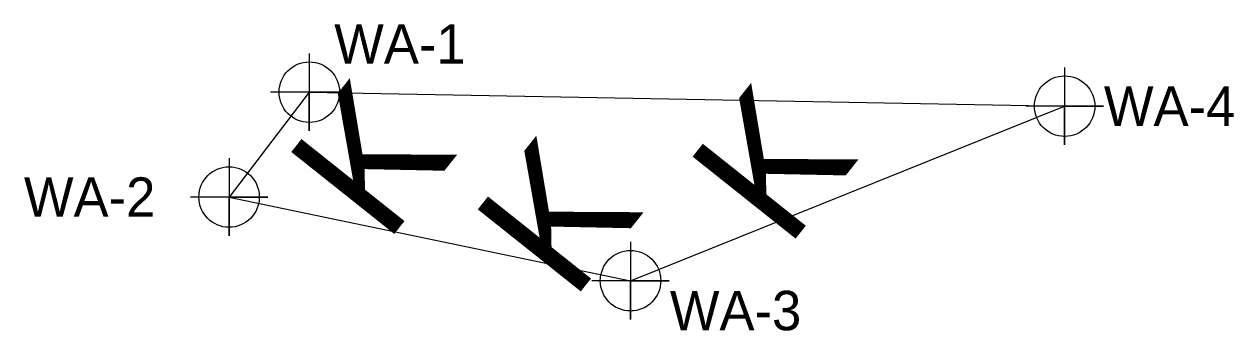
# Model space of a CAD drawing. Extents: x 1487542 to 1488992, y 498221 to 499418.
# Drawn here: x 1488898 to 1488991.8, y 499394.7 to 499418.4 of the extents above; entities that cross this region are included whole.
import ezdxf

# ---------------------------------------------------------------- set-up
doc = ezdxf.new("R2010")
doc.units = 0
for name, color, linetype in [('Exist Environmental Wetland Boundary', 7, 'Continuous'), ('Exist Environmental Wetland Boundary Cogo Point CELL', 7, 'Continuous'), ('Exist Environmental Wetland Boundary Text', 7, 'Continuous')]:
    doc.layers.add(name, color=color, linetype=linetype)

msp = doc.modelspace()

# ---------------------------------------------------------------- linework, layer by layer
at = {"layer": 'Exist Environmental Wetland Boundary'}
for p, q in [((1488920.102, 499413.146), (1488913.881, 499405.028)), ((1488920.102, 499413.146), (1488978.656, 499412.061)), ((1488945.005, 499398.55), (1488978.656, 499412.061)), ((1488913.881, 499405.028), (1488945.005, 499398.55))]:
    msp.add_line(p, q, dxfattribs=at)
at = {"layer": 'Exist Environmental Wetland Boundary Cogo Point CELL'}
for points in [[(1488920.102, 499416.146), (1488920.102, 499410.146), (1488920.102, 499413.146), (1488923.102, 499413.146), (1488917.102, 499413.146)], [(1488978.656, 499415.061), (1488978.656, 499409.061), (1488978.656, 499412.061), (1488981.656, 499412.061), (1488975.656, 499412.061)], [(1488913.881, 499408.028), (1488913.881, 499402.028), (1488913.881, 499405.028), (1488916.881, 499405.028), (1488910.881, 499405.028)], [(1488945.005, 499401.55), (1488945.005, 499395.55), (1488945.005, 499398.55), (1488948.005, 499398.55), (1488942.005, 499398.55)]]:
    msp.add_lwpolyline(points, dxfattribs=at)
for centre in [(1488920.102, 499413.146), (1488978.656, 499412.061), (1488913.881, 499405.028), (1488945.005, 499398.55)]:
    msp.add_circle(centre, 2.344, dxfattribs=at)

# ---------------------------------------------------------------- texts
at = {"layer": 'Exist Environmental Wetland Boundary'}
for p in [(1488925.991, 499401.296), (1488957.104, 499400.933), (1488940.451, 499396.847)]:
    msp.add_text('K', height=10.2, rotation=51.5264, dxfattribs=at).set_placement(p)
at = {"layer": 'Exist Environmental Wetland Boundary Text'}
for s, p in [('WA-1', (1488922.031, 499415.358)), ('WA-4', (1488981.703, 499410.538)), ('WA-2', (1488897.979, 499403.504)), ('WA-3', (1488948.052, 499394.718))]:
    msp.add_text(s, height=3.0471, dxfattribs=at).set_placement(p)

doc.saveas('drawing.dxf')
